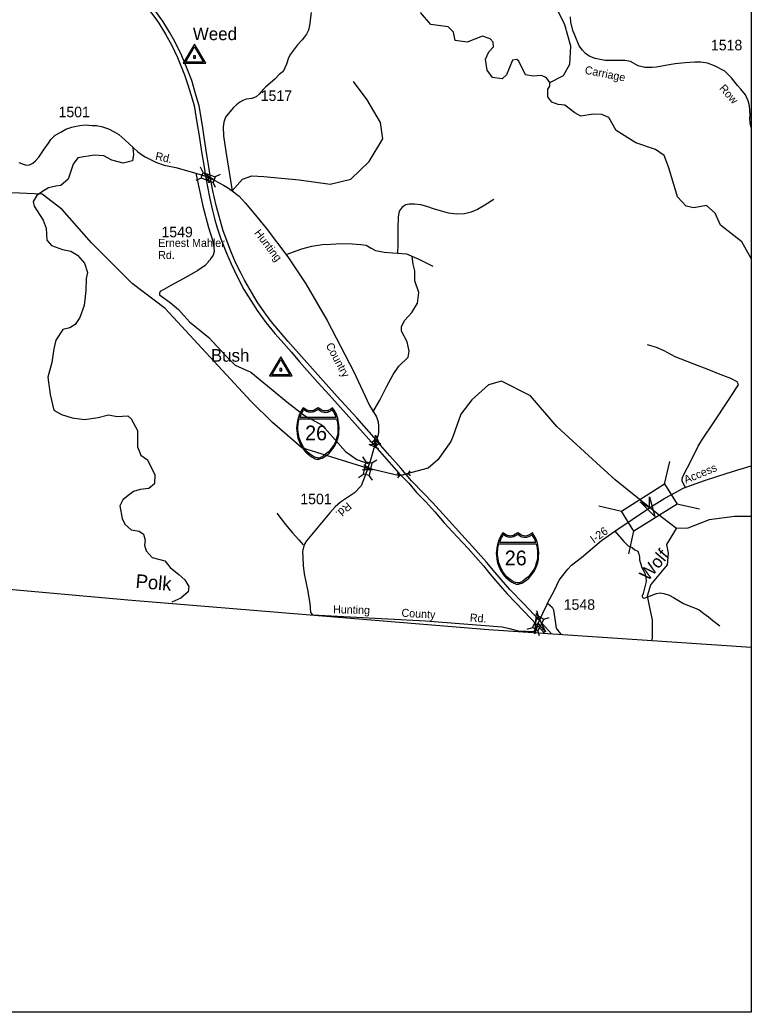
# Model space of a CAD drawing. Extents: x 990631 to 1056237, y 535999 to 585651.
# Drawn here: x 1047553 to 1056237, y 535999 to 547778 of the extents above; entities that cross this region are included whole.
import ezdxf

# ---------------------------------------------------------------- set-up
doc = ezdxf.new("R2010")
doc.units = 0
for name, color, linetype in [('Exist Boundary Political CountyLine Label', 7, 'Continuous'), ('Exist Boundary Political StateLine', 7, 'Continuous'), ('Exist Hydrographic Creek Single Shore', 7, 'Continuous'), ('Exist Hydrographic Creek Single Shore Label', 7, 'Continuous'), ('Exist Hydrographic Misc Water Feature', 7, 'Continuous'), ('Exist Hydrographic River Shore', 7, 'Continuous'), ('Exist Road Non-System Type 51', 7, 'Continuous'), ('Exist Road Primary Interstate Divided Center Attributed', 7, 'Continuous'), ('Exist Road Primary Interstate Shield CELL', 7, 'Continuous'), ('Exist Road Primary Interstate Shield Number Label', 7, 'Continuous'), ('Exist Road Primary Interstate Structure Standard Bridge CELL', 7, 'Continuous'), ('Exist Road Secondary Structure Culvert CELL', 7, 'Continuous'), ('Exist Road Secondary Structure Standard Bridge Attributed CELL', 7, 'Continuous'), ('Exist Road Secondary Structure Standard Bridge CELL', 7, 'Continuous'), ('Exist Road Secondary Type 41 Attributed', 7, 'Continuous'), ('Exist Road Secondary Type 51 Attributed', 7, 'Continuous'), ('Exist Road Secondary Type 51 Label', 7, 'Continuous'), ('Exist Road Secondary Type 51 Number Label', 7, 'Continuous'), ('Exist Survey Geodetic Marker CELL', 7, 'Continuous'), ('Exist Survey Geodetic Marker Label', 7, 'Continuous'), ('Scratch_Level_3', 7, 'Continuous')]:
    doc.layers.add(name, color=color, linetype=linetype)

msp = doc.modelspace()

# ---------------------------------------------------------------- linework, layer by layer
at = {"layer": 'Exist Boundary Political StateLine'}
msp.add_lwpolyline([(1021828, 543845), (1022272, 543788), (1023519, 543604), (1025261, 543357), (1027988, 542972), (1030939, 542599), (1033618, 542331), (1035851, 542120), (1038357, 541881), (1041739, 541546), (1044776, 541259), (1048837, 540895), (1053118, 540541), (1056237, 540333)], dxfattribs=at)
at = {"layer": 'Exist Hydrographic Creek Single Shore'}
for points in [[(1053845, 547033), (1054008, 547116), (1054085, 547252), (1054096, 547467), (1054026, 547717), (1053932, 547903)], [(1055350, 541739), (1055183, 541867), (1055011, 542004), (1054621, 542317), (1054402, 542519), (1053930, 542952), (1053616, 543313), (1053272, 543490), (1053120, 543444), (1052922, 543268), (1052791, 543096), (1052700, 542841), (1052673, 542774), (1052515, 542554), (1052403, 542458), (1052267, 542419), (1052060, 542366), (1051677, 542457), (1050902, 542699), (1050554, 543000), (1050295, 543252), (1049280, 544352), (1048889, 544649), (1048404, 545131), (1048058, 545525), (1047818, 545710), (1047367, 545727)], [(1056237, 541882), (1056038, 541882), (1055737, 541842), (1055484, 541743), (1055350, 541739)]]:
    msp.add_lwpolyline(points, dxfattribs=at)
at = {"layer": 'Exist Hydrographic Misc Water Feature'}
for points in [[(1055039, 540782), (1055008, 540941), (1055045, 541072), (1055245, 541308), (1055257, 541448), (1055236, 541551), (1055350, 541739)], [(1055055, 540405), (1055066, 540438), (1055065, 540655), (1055039, 540782)]]:
    msp.add_lwpolyline(points, dxfattribs=at)
at = {"layer": 'Exist Hydrographic River Shore'}
for points in [[(1053845, 547036), (1053808, 547089), (1053748, 547116), (1053650, 547108), (1053556, 547124), (1053478, 547287), (1053454, 547309), (1053403, 547298), (1053334, 547127), (1053279, 547076), (1053164, 547092), (1053102, 547180), (1053083, 547311), (1053121, 547400), (1053177, 547456), (1053174, 547512), (1053137, 547552), (1053049, 547584), (1052865, 547512), (1052724, 547531), (1052702, 547632), (1052639, 547695), (1052433, 547724), (1052311, 547865)], [(1056237, 544947), (1056126, 545143), (1055874, 545340), (1055811, 545483), (1055706, 545576), (1055555, 545546), (1055466, 545568), (1055362, 545679), (1055259, 546021), (1055204, 546168), (1055103, 546239), (1054868, 546319), (1054633, 546466), (1054549, 546619), (1054466, 546654), (1054362, 546659), (1054215, 546635), (1054142, 546675), (1054025, 546764), (1053947, 546774), (1053870, 546801), (1053824, 546864), (1053824, 546955), (1053846, 546990), (1053848, 547033)]]:
    msp.add_lwpolyline(points, dxfattribs=at)
at = {"layer": 'Exist Road Non-System Type 51'}
for points in [[(1050076, 545749), (1050198, 545885), (1050307, 545927), (1050450, 545919), (1050870, 545877), (1051240, 545826), (1051484, 545885), (1051702, 546095), (1051862, 546364), (1051837, 546558), (1051677, 546827), (1051517, 547045)], [(1056237, 546613), (1056220, 546611)], [(1048895, 546259), (1048904, 546179), (1048891, 546103), (1048782, 546078), (1048647, 546112), (1048551, 546162), (1048437, 546171), (1048244, 546141), (1048185, 546066), (1048156, 545969), (1048126, 545885), (1048042, 545813), (1047979, 545805), (1047895, 545784), (1047811, 545733), (1047757, 545691), (1047710, 545620), (1047723, 545565), (1047832, 545401), (1047866, 545305), (1047874, 545162), (1047929, 545099), (1048059, 545052), (1048160, 545031), (1048240, 544985), (1048320, 544889), (1048358, 544779), (1048341, 544708), (1048337, 544565), (1048316, 544388), (1048265, 544244), (1048210, 544160), (1048147, 544122), (1048063, 544101), (1047979, 543975), (1047958, 543874), (1047933, 543710), (1047887, 543538), (1047912, 543332), (1047958, 543143), (1048047, 543092), (1048173, 543055), (1048320, 543033), (1048484, 543059), (1048605, 543088), (1048711, 543071), (1048837, 543076), (1048874, 543042), (1048950, 542903), (1048950, 542826), (1048950, 542708), (1048992, 542611), (1049068, 542557), (1049156, 542376), (1049152, 542271), (1049084, 542216), (1048984, 542204), (1048904, 542178), (1048841, 542132), (1048778, 542082), (1048740, 542010), (1048769, 541859), (1048799, 541792), (1048874, 541725), (1048971, 541708), (1049021, 541674), (1049042, 541603), (1049034, 541544), (1049055, 541476), (1049126, 541397), (1049274, 541355), (1049337, 541279), (1049442, 541195), (1049513, 541132), (1049559, 541052), (1049551, 540989), (1049467, 540913), (1049358, 540867)], [(1053182, 545646), (1053075, 545577), (1052986, 545526), (1052911, 545496), (1052832, 545477), (1052740, 545470), (1052642, 545485), (1052561, 545508), (1052465, 545533), (1052386, 545561), (1052313, 545584), (1052239, 545590), (1052177, 545592), (1052135, 545581), (1052092, 545553), (1052058, 545506), (1052044, 545440), (1052042, 545306), (1052040, 545112), (1052038, 545010)], [(1050716, 544993), (1050903, 545060), (1051020, 545091), (1051145, 545111), (1051245, 545117), (1051368, 545124), (1051500, 545121), (1051601, 545112), (1051667, 545102), (1051724, 545068), (1051775, 545042), (1051841, 545028), (1051881, 545019), (1051977, 545014), (1052038, 545010)], [(1052038, 545010), (1052144, 545001), (1052292, 544938), (1052456, 544854)], [(1049796, 544922), (1049790, 544902), (1049754, 544861), (1049666, 544802), (1049538, 544728), (1049348, 544626), (1049263, 544577), (1049220, 544552), (1049211, 544532), (1049211, 544512), (1049238, 544493), (1049338, 544422), (1049437, 544339), (1049569, 544194)], [(1051746, 543120), (1051828, 543265), (1051912, 543428), (1051988, 543567), (1052055, 543668), (1052164, 543773), (1052177, 543845), (1052151, 543954), (1052084, 544084), (1052084, 544139), (1052126, 544215), (1052210, 544303), (1052277, 544416), (1052290, 544542), (1052244, 544681), (1052244, 544799), (1052223, 544879), (1052214, 544967)], [(1049569, 544194), (1049799, 544007), (1049992, 543797), (1050110, 543679), (1050295, 543595), (1050563, 543377), (1050723, 543242), (1050933, 543082), (1051143, 542965), (1051421, 542654), (1051555, 542561), (1051690, 542511)], [(1055463, 542220), (1055427, 542287), (1055418, 542308), (1055417, 542330), (1055428, 542359), (1055534, 542564), (1055607, 542716), (1055658, 542800), (1055799, 543008), (1055952, 543239), (1056013, 543331), (1056070, 543420), (1056087, 543445), (1056085, 543459), (1056072, 543480), (1055997, 543520), (1055849, 543577), (1055733, 543625), (1055549, 543696), (1055335, 543777), (1055203, 543850), (1055112, 543889), (1055007, 543920)], [(1050607, 541924), (1050708, 541786), (1050791, 541690), (1050865, 541605), (1050919, 541548)]]:
    msp.add_lwpolyline(points, dxfattribs=at)
at = {"layer": 'Exist Road Primary Interstate Divided Center Attributed'}
for p, q in [((1053868, 540491), (1053724, 540649)), ((1053697, 540592), (1053785, 540496))]:
    msp.add_line(p, q, dxfattribs=at)
for points in [[(1048648, 548343), (1048842, 548163), (1048955, 548053), (1049062, 547927), (1049144, 547821), (1049204, 547738), (1049284, 547609), (1049357, 547473), (1049425, 547329), (1049509, 547124), (1049550, 547008), (1049582, 546891), (1049622, 546762), (1049657, 546560), (1049681, 546403), (1049712, 546213), (1049746, 546005), (1049757, 545922)], [(1049819, 545894), (1049803, 546008), (1049773, 546174), (1049742, 546385), (1049721, 546523), (1049684, 546757), (1049645, 546887), (1049594, 547059), (1049542, 547197), (1049477, 547351), (1049390, 547529), (1049331, 547632), (1049250, 547761), (1049157, 547893), (1049071, 547998), (1048972, 548111), (1048724, 548356)], [(1049757, 545922), (1049781, 545794), (1049809, 545654), (1049840, 545515), (1049868, 545405), (1049898, 545311), (1049941, 545180), (1050006, 545008), (1050061, 544880), (1050130, 544738), (1050215, 544579), (1050298, 544447), (1050373, 544329), (1050474, 544185), (1050580, 544054), (1050657, 543971), (1050778, 543833), (1050876, 543719), (1050965, 543617), (1051093, 543473), (1051225, 543326), (1051495, 543028), (1051766, 542725)], [(1051789, 542788), (1051555, 543052), (1051320, 543306), (1050735, 543964), (1050538, 544199), (1050462, 544302), (1050373, 544432), (1050221, 544687), (1050183, 544766), (1050114, 544898), (1050057, 545031), (1049969, 545275), (1049884, 545574), (1049847, 545749), (1049819, 545894)], [(1053724, 540649), (1053536, 540849), (1053372, 541018), (1053267, 541136), (1053198, 541219), (1053095, 541340), (1052963, 541488), (1052802, 541665), (1052616, 541869), (1052452, 542049), (1052345, 542158), (1052204, 542308), (1052077, 542456), (1051945, 542602), (1051836, 542731), (1051789, 542788)], [(1051766, 542725), (1052052, 542397), (1052171, 542278), (1052265, 542167), (1052373, 542055), (1052482, 541940), (1052592, 541807), (1052748, 541641), (1052876, 541503), (1053059, 541297), (1053135, 541203), (1053201, 541124), (1053342, 540966), (1053539, 540758), (1053697, 540592)]]:
    msp.add_lwpolyline(points, dxfattribs=at)
at = {"layer": 'Exist Road Primary Interstate Shield CELL'}
for points in [[(1051094, 542563), (1051103, 542564), (1051116, 542566), (1051128, 542570), (1051142, 542576), (1051163, 542588), (1051180, 542598), (1051199, 542611), (1051225, 542634), (1051251, 542662), (1051274, 542693), (1051293, 542722), (1051309, 542755), (1051322, 542786), (1051333, 542821), (1051340, 542856), (1051343, 542891), (1051346, 542931), (1051343, 542975), (1051335, 543021), (1051328, 543049), (1051317, 543083), (1051308, 543105), (1051287, 543143), (1051268, 543173), (1051241, 543154), (1051224, 543144), (1051213, 543139), (1051202, 543137), (1051181, 543135), (1051168, 543135), (1051156, 543138), (1051146, 543140), (1051138, 543144), (1051094, 543173), (1051049, 543144), (1051040, 543140), (1051031, 543138), (1051021, 543136), (1051006, 543135), (1050995, 543135), (1050983, 543137), (1050973, 543139), (1050963, 543144), (1050918, 543173), (1050900, 543147), (1050886, 543122), (1050870, 543086), (1050861, 543058), (1050854, 543035), (1050846, 542993), (1050841, 542957), (1050840, 542931), (1050845, 542866), (1050852, 542832), (1050859, 542804), (1050883, 542744), (1050901, 542711), (1050917, 542686), (1050938, 542659), (1050950, 542646), (1050995, 542607), (1051025, 542587), (1051049, 542574), (1051060, 542569), (1051077, 542565)], [(1050923, 543152), (1050912, 543135), (1050899, 543112), (1050889, 543089), (1050879, 543063), (1051311, 543062), (1051301, 543085), (1051290, 543107), (1051278, 543128), (1051265, 543148), (1051241, 543133), (1051223, 543124), (1051209, 543119), (1051197, 543117), (1051178, 543115), (1051170, 543116), (1051144, 543122), (1051126, 543129), (1051110, 543140), (1051096, 543153), (1051062, 543132), (1051047, 543125), (1051029, 543121), (1051010, 543118), (1050981, 543122), (1050958, 543130), (1050938, 543140)], [(1051313, 543041), (1051318, 543029), (1051324, 543002), (1051327, 542981), (1051331, 542957), (1051330, 542916), (1051328, 542873), (1051324, 542848), (1051319, 542825), (1051311, 542800), (1051300, 542766), (1051284, 542737), (1051264, 542705), (1051243, 542678), (1051233, 542666), (1051216, 542647), (1051183, 542621), (1051160, 542604), (1051132, 542587), (1051117, 542581), (1051101, 542577), (1051087, 542578), (1051070, 542583), (1051057, 542586), (1051027, 542602), (1051004, 542618), (1050964, 542651), (1050942, 542676), (1050922, 542705), (1050904, 542736), (1050885, 542775), (1050872, 542815), (1050862, 542858), (1050856, 542911), (1050855, 542943), (1050857, 542974), (1050860, 542990), (1050864, 543010), (1050871, 543041)], [(1053465, 541079), (1053474, 541080), (1053487, 541083), (1053499, 541087), (1053513, 541093), (1053534, 541104), (1053551, 541114), (1053570, 541127), (1053596, 541151), (1053622, 541178), (1053645, 541209), (1053664, 541238), (1053680, 541272), (1053693, 541303), (1053704, 541338), (1053711, 541372), (1053714, 541408), (1053717, 541447), (1053714, 541492), (1053706, 541537), (1053699, 541566), (1053688, 541600), (1053679, 541621), (1053658, 541660), (1053639, 541689), (1053612, 541670), (1053594, 541661), (1053584, 541656), (1053572, 541654), (1053552, 541651), (1053539, 541652), (1053527, 541655), (1053517, 541657), (1053509, 541661), (1053465, 541689), (1053420, 541661), (1053411, 541657), (1053401, 541655), (1053392, 541652), (1053377, 541651), (1053366, 541652), (1053354, 541654), (1053344, 541656), (1053334, 541661), (1053289, 541689), (1053271, 541664), (1053257, 541638), (1053241, 541602), (1053232, 541575), (1053225, 541552), (1053216, 541510), (1053212, 541473), (1053211, 541447), (1053216, 541383), (1053223, 541348), (1053230, 541321), (1053254, 541261), (1053272, 541227), (1053288, 541203), (1053309, 541176), (1053321, 541163), (1053366, 541124), (1053396, 541103), (1053420, 541090), (1053431, 541086), (1053448, 541081)], [(1053294, 541669), (1053283, 541652), (1053270, 541629), (1053260, 541605), (1053250, 541579), (1053681, 541579), (1053671, 541601), (1053661, 541624), (1053649, 541644), (1053636, 541664), (1053611, 541649), (1053594, 541641), (1053580, 541636), (1053568, 541633), (1053549, 541632), (1053541, 541632), (1053515, 541638), (1053497, 541645), (1053481, 541656), (1053467, 541669), (1053433, 541648), (1053418, 541642), (1053400, 541637), (1053381, 541635), (1053352, 541638), (1053329, 541646), (1053309, 541656)], [(1053684, 541558), (1053689, 541545), (1053695, 541518), (1053698, 541498), (1053702, 541474), (1053701, 541432), (1053699, 541390), (1053695, 541365), (1053689, 541342), (1053682, 541316), (1053671, 541282), (1053655, 541254), (1053635, 541222), (1053613, 541194), (1053604, 541183), (1053586, 541164), (1053554, 541138), (1053531, 541120), (1053503, 541104), (1053488, 541097), (1053472, 541094), (1053458, 541095), (1053441, 541099), (1053428, 541103), (1053398, 541119), (1053374, 541135), (1053335, 541167), (1053313, 541193), (1053293, 541222), (1053275, 541252), (1053256, 541292), (1053243, 541332), (1053233, 541375), (1053226, 541427), (1053226, 541459), (1053228, 541490), (1053231, 541506), (1053235, 541526), (1053242, 541557)]]:
    msp.add_lwpolyline(points, close=True, dxfattribs=at)
at = {"layer": 'Exist Road Primary Interstate Structure Standard Bridge CELL'}
for p, q in [((1051737, 542765), (1051711, 542769)), ((1051799, 542733), (1051752, 542780)), ((1051768, 542796), (1051763, 542822)), ((1051788, 542692), (1051783, 542718)), ((1051841, 542745), (1051815, 542749))]:
    msp.add_line(p, q, dxfattribs=at)
msp.add_lwpolyline([(1051815, 542749), (1051768, 542796), (1051736, 542765), (1051783, 542718)], close=True, dxfattribs=at)
at = {"layer": 'Exist Road Secondary Structure Culvert CELL'}
for p, q in [((1052184, 542423), (1052161, 542389)), ((1052033, 542398), (1052065, 542373)), ((1052043, 542340), (1052065, 542373)), ((1052065, 542373), (1052161, 542389)), ((1052193, 542365), (1052161, 542389))]:
    msp.add_line(p, q, dxfattribs=at)
at = {"layer": 'Exist Road Secondary Structure Standard Bridge Attributed CELL'}
for points in [[(1049802, 545845), (1049748, 545954), (1049849, 545887), (1049788, 545909)], [(1051767, 542728), (1051778, 542850), (1051829, 542739), (1051788, 542790)], [(1051812, 542684), (1051703, 542739), (1051825, 542746), (1051763, 542727)], [(1051638, 542497), (1051744, 542437), (1051622, 542435), (1051685, 542452)], [(1055029, 542118), (1055092, 541882), (1054920, 542055), (1055031, 541988)], [(1053670, 540491), (1053687, 540735), (1053794, 540515), (1053710, 540615)]]:
    msp.add_lwpolyline(points, close=True, dxfattribs=at)
at = {"layer": 'Exist Road Secondary Structure Standard Bridge CELL'}
for p, q in [((1049729, 545965), (1049700, 546028)), ((1049934, 545944), (1049872, 545915)), ((1049706, 545900), (1049643, 545871)), ((1049877, 545786), (1049848, 545848)), ((1051666, 542532), (1051628, 542590)), ((1051733, 542518), (1051791, 542556)), ((1055208, 542268), (1055270, 542537)), ((1051576, 542347), (1051634, 542385)), ((1051740, 542312), (1051703, 542370)), ((1054427, 542009), (1054696, 541947)), ((1055355, 542034), (1055624, 541973)), ((1054784, 541439), (1054846, 541708)), ((1053713, 540698), (1053693, 540764)), ((1053774, 540665), (1053840, 540685)), ((1053576, 540544), (1053642, 540564)), ((1053725, 540465), (1053704, 540531))]:
    msp.add_line(p, q, dxfattribs=at)
for points in [[(1049848, 545848), (1049706, 545900), (1049730, 545967), (1049872, 545915)], [(1051634, 542385), (1051665, 542532), (1051734, 542518), (1051703, 542370)], [(1054696, 541947), (1055208, 542269), (1055358, 542030), (1054846, 541708)], [(1053642, 540564), (1053713, 540698), (1053775, 540665), (1053704, 540531)]]:
    msp.add_lwpolyline(points, close=True, dxfattribs=at)
at = {"layer": 'Exist Road Secondary Type 41 Attributed'}
for points in [[(1056237, 546500), (1056225, 546547), (1056220, 546611), (1056225, 546651), (1056219, 546757), (1056203, 546818), (1056169, 546887), (1056114, 546956), (1056075, 547000), (1056002, 547091), (1055923, 547170), (1055804, 547233), (1055717, 547262), (1055641, 547274), (1055567, 547274), (1055453, 547268), (1055335, 547254), (1055241, 547239), (1055112, 547217), (1055060, 547212), (1054975, 547212), (1054897, 547234), (1054804, 547282), (1054743, 547296), (1054610, 547296), (1054505, 547294), (1054386, 547318), (1054313, 547347), (1054270, 547378), (1054233, 547419), (1054195, 547469), (1054145, 547596), (1054118, 547651), (1054098, 547750), (1054092, 547814)], [(1054620, 541709), (1054726, 541585), (1054776, 541535), (1054825, 541513), (1054855, 541488), (1054890, 541470), (1054904, 541436), (1054911, 541402), (1054911, 541370), (1054922, 541328), (1054940, 541278), (1054974, 541211), (1054988, 541158), (1054991, 541110), (1054954, 540967), (1054945, 540942), (1054948, 540922), (1054963, 540915), (1054984, 540917), (1055051, 540943), (1055113, 540967), (1055155, 540975), (1055201, 540968), (1055264, 540947), (1055316, 540920), (1055435, 540851), (1055522, 540813), (1055564, 540800), (1055619, 540775), (1055677, 540732), (1055730, 540692), (1055784, 540649), (1055864, 540586)], [(1053821, 540852), (1053875, 540808), (1053889, 540774), (1053913, 540612), (1053923, 540556), (1053952, 540513), (1053982, 540483)]]:
    msp.add_lwpolyline(points, dxfattribs=at)
at = {"layer": 'Exist Road Secondary Type 51 Attributed'}
for points in [[(1051011, 547867), (1050993, 547712), (1050980, 547654), (1050958, 547608), (1050933, 547575), (1050905, 547540), (1050849, 547480), (1050769, 547372), (1050743, 547328), (1050721, 547253), (1050680, 547166), (1050634, 547128), (1050584, 547076), (1050526, 547026), (1050475, 546983), (1050442, 546952), (1050394, 546894), (1050359, 546865), (1050309, 546846), (1050240, 546835), (1050200, 546821), (1050166, 546801), (1050125, 546771), (1050091, 546739), (1050026, 546663), (1049997, 546621), (1049975, 546563), (1049969, 546506), (1049971, 546400), (1050000, 546215), (1050076, 545749)], [(1047541, 546085), (1047593, 546064), (1047632, 546053), (1047667, 546055), (1047707, 546077), (1047738, 546103), (1047780, 546149), (1047843, 546241), (1047894, 546316), (1047921, 546359), (1047971, 546410), (1048040, 546446), (1048101, 546481), (1048172, 546504), (1048221, 546516), (1048267, 546524), (1048335, 546530), (1048411, 546525), (1048462, 546523), (1048481, 546519), (1048524, 546511), (1048605, 546486), (1048675, 546449), (1048729, 546418), (1048801, 546354), (1048955, 546213), (1048999, 546180), (1049042, 546150), (1049105, 546119), (1049177, 546083), (1049267, 546051), (1049406, 546024), (1049642, 545958)], [(1049642, 545958), (1049757, 545922)], [(1049642, 545958), (1049727, 545568), (1049793, 545315), (1049846, 545150), (1049856, 545074), (1049862, 545028), (1049848, 544985), (1049818, 544942), (1049805, 544918)], [(1049757, 545922), (1049790, 545908), (1049819, 545894)], [(1049819, 545894), (1049847, 545881), (1049869, 545870), (1049911, 545847), (1049971, 545815), (1050019, 545789), (1050076, 545749)], [(1050076, 545749), (1050157, 545684), (1050231, 545604), (1050373, 545435), (1050479, 545304), (1050735, 544966), (1050950, 544646), (1051201, 544208), (1051519, 543601), (1051707, 543201), (1051787, 543067), (1051809, 543007), (1051812, 542953), (1051812, 542889), (1051809, 542853), (1051789, 542788)], [(1051789, 542788), (1051770, 542737), (1051766, 542725)], [(1051766, 542725), (1051755, 542694), (1051734, 542608), (1051708, 542528), (1051694, 542483), (1051686, 542453)], [(1051686, 542453), (1051608, 542248), (1051529, 542164), (1051363, 542052), (1051299, 541996), (1051235, 541927), (1050956, 541594), (1050939, 541563), (1050921, 541518), (1050909, 541469), (1050914, 541399), (1050916, 541301), (1050929, 541202), (1050968, 541011), (1050996, 540849), (1051005, 540745), (1051028, 540714), (1052369, 540643), (1053281, 540575), (1053367, 540553), (1053469, 540526), (1053660, 540516), (1053697, 540592)], [(1055030, 541986), (1055055, 542003), (1055214, 542101), (1055338, 542169), (1055431, 542219), (1055682, 542309), (1055840, 542360), (1056016, 542417), (1056237, 542483)], [(1053821, 540852), (1053847, 540907), (1053903, 541009), (1053957, 541126), (1054013, 541199), (1054061, 541257), (1054105, 541305), (1054224, 541395), (1054459, 541597), (1054620, 541709), (1055030, 541986)], [(1053724, 540649), (1053765, 540735), (1053817, 540843), (1053821, 540852)], [(1053697, 540592), (1053710, 540620), (1053724, 540649)]]:
    msp.add_lwpolyline(points, dxfattribs=at)
at = {"layer": 'Exist Survey Geodetic Marker CELL'}
for points in [[(1049761, 547264), (1049627, 547490), (1049494, 547264)], [(1049735, 547276), (1049520, 547276), (1049627, 547458)], [(1049640, 547323), (1049640, 547351), (1049615, 547351), (1049615, 547323)], [(1050787, 543552), (1050653, 543778), (1050519, 543552)], [(1050761, 543564), (1050545, 543564), (1050653, 543746)], [(1050665, 543611), (1050665, 543639), (1050641, 543639), (1050641, 543611)]]:
    msp.add_lwpolyline(points, close=True, dxfattribs=at)
at = {"layer": 'Scratch_Level_3'}
msp.add_lwpolyline([(1056237, 535999), (990631, 535999), (990631, 585651), (1056237, 585651)], close=True, dxfattribs=at)

# ---------------------------------------------------------------- texts
at = {"layer": 'Exist Boundary Political CountyLine Label'}
msp.add_text('Polk', height=164, rotation=355.1577, dxfattribs=at).set_placement((1048923, 541036))
at = {"layer": 'Exist Hydrographic Creek Single Shore Label'}
msp.add_text('Wolf', height=150, rotation=49.6626, dxfattribs=at).set_placement((1055011, 541108))
at = {"layer": 'Exist Road Primary Interstate Shield Number Label'}
for p in [(1050941, 542787), (1053312, 541303)]:
    msp.add_text('26', height=175, dxfattribs=at).set_placement(p)
at = {"layer": 'Exist Road Secondary Type 51 Label'}
for s, rotation, p in [('Carriage', 348.7955, (1054256, 547140)), ('Row', 311.471, (1055853, 546961)), ('Rd.', 347.8378, (1049156, 546118)), ('Hunting', 307.427, (1050332, 545247)), ('Country', 298.1782, (1051183, 543915)), ('Access', 22.5098, (1055462, 542271)), ('Rd.', 221.2657, (1051441, 542059)), ('I-26 ', 35.7841, (1054369, 541561)), ('Hunting', 358.5878, (1051272, 540735)), ('County', 356.5869, (1052083, 540694)), ('Rd.', 355.9999, (1052894, 540637))]:
    msp.add_text(s, height=95, rotation=rotation, dxfattribs=at).set_placement(p)
for s, p in [('Ernest Mahler', (1049196, 545083)), ('Rd.', (1049196, 544939))]:
    msp.add_text(s, height=95, dxfattribs=at).set_placement(p)
at = {"layer": 'Exist Road Secondary Type 51 Number Label'}
for s, p in [('1518', (1055760, 547416)), ('1517', (1050414, 546815)), ('1501', (1048013, 546622)), ('1549', (1049235, 545197)), ('1501', (1050884, 542028)), ('1548', (1054012, 540775))]:
    msp.add_text(s, height=125, dxfattribs=at).set_placement(p)
at = {"layer": 'Exist Survey Geodetic Marker Label'}
for s, p in [('Weed', (1049608, 547537)), ('Bush', (1049822, 543720))]:
    msp.add_text(s, height=150, dxfattribs=at).set_placement(p)

doc.saveas('drawing.dxf')
